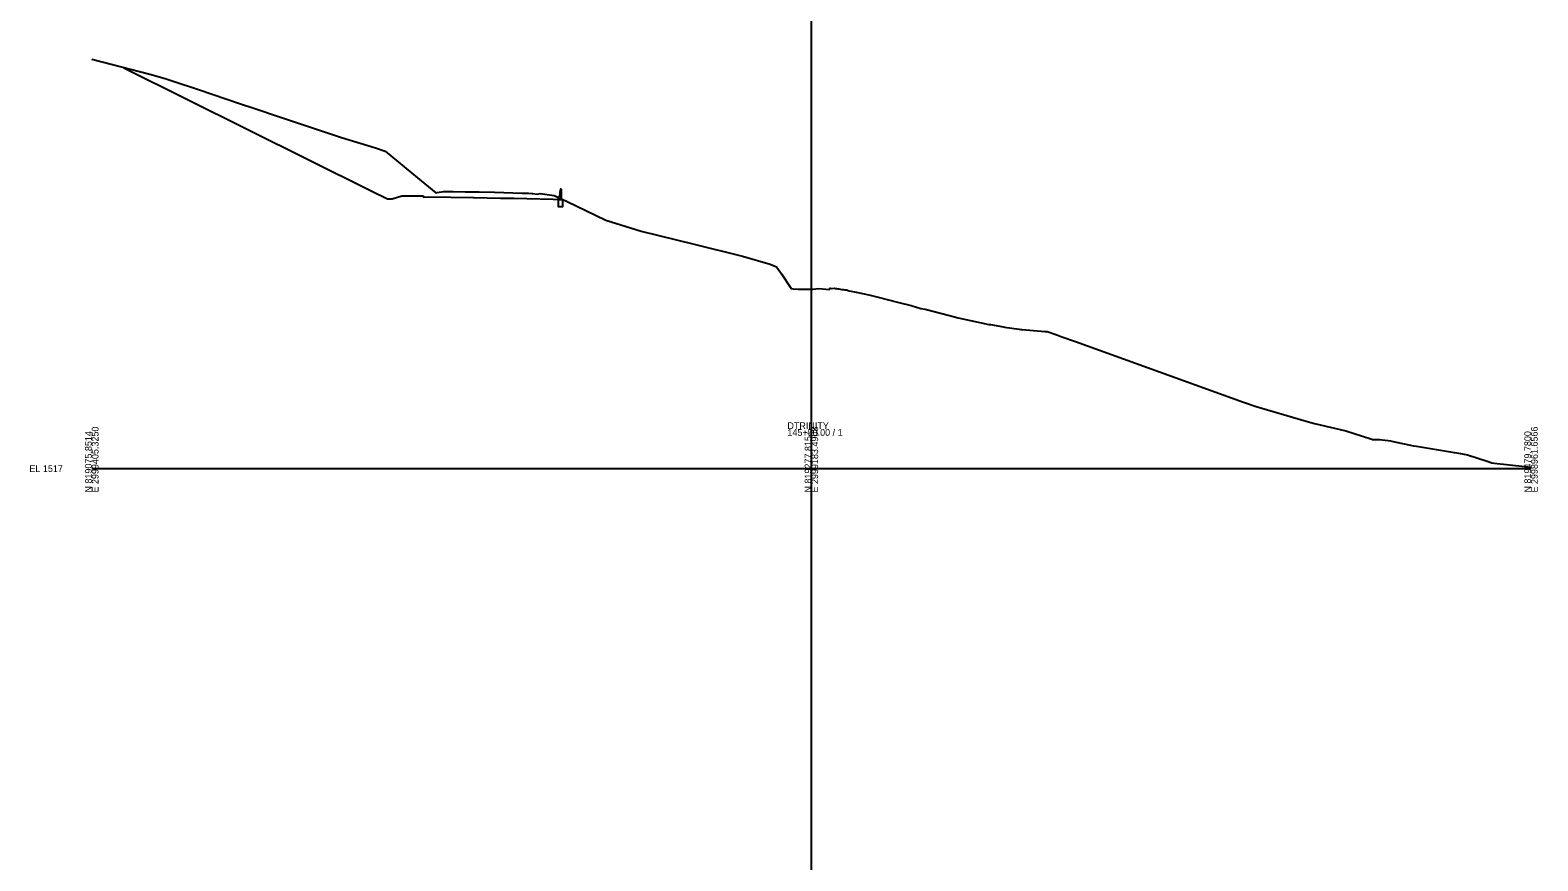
# Model space of a CAD drawing. Extents: x -26 to 603, y -10 to 4805.
# Drawn here: x -26 to 603, y 337 to 683 of the extents above; entities that cross this region are included whole.
import ezdxf

# ---------------------------------------------------------------- set-up
doc = ezdxf.new("R2010")
doc.units = 0
for name, color, linetype in [('DESIGN - SCRATCH - User 1', 7, 'Continuous'), ('DESIGN - SHEET - Light Grid', 7, 'Continuous'), ('DESIGN - TYPICAL - Finished Grade and Subgrade', 7, 'Continuous'), ('SURVEY - GROUND - Top of Ground', 7, 'Continuous')]:
    doc.layers.add(name, color=color, linetype=linetype)

msp = doc.modelspace()

# ---------------------------------------------------------------- linework, layer by layer
at = {"layer": 'DESIGN - SCRATCH - User 1'}
for p, q in [((195.27, 616.35), (194.96, 613.45)), ((195.78, 616.4), (195.33, 616.4)), ((195.78, 612.15), (195.78, 616.4)), ((194.36, 612.38), (194.36, 612.15)), ((194.82, 613.06), (194.37, 612.42))]:
    msp.add_line(p, q, dxfattribs=at)
msp.add_lwpolyline([(194.36, 612.15), (194.36, 609.15), (196.36, 609.15), (196.36, 612.16)], dxfattribs=at)
for centre, radius, start, end in [((194.44, 612.38), 0.0833, 145.00798, 180), ((194.14, 613.54), 0.833, 325.00798, 353.99099)]:
    msp.add_arc(centre, radius, start, end, dxfattribs=at)
at = {"layer": 'DESIGN - SHEET - Light Grid'}
for p, q in [((300, 500), (300, 1012.01)), ((300, 0), (300, 516.44)), ((0, 500), (300, 500)), ((300, 500), (600, 500))]:
    msp.add_line(p, q, dxfattribs=at)
at = {"layer": 'DESIGN - TYPICAL - Finished Grade and Subgrade'}
msp.add_lwpolyline([(13.36, 667.06), (116.43, 615.76), (123.26, 612.37), (124.26, 612.37), (125.26, 612.37), (129.26, 613.71), (130.27, 613.7), (135.27, 613.63), (136.77, 613.61), (137.78, 613.6), (138.27, 613.58), (138.28, 613.1), (140.28, 613.27), (158.95, 612.93), (159.3, 612.92), (170.32, 612.72), (175.88, 612.62), (181.34, 612.52), (192.36, 612.32), (194.36, 612.15), (196.32, 612.16)], dxfattribs=at)
at = {"layer": 'SURVEY - GROUND - Top of Ground'}
msp.add_line((410.1, 552.89), (480.12, 527.62), dxfattribs=at)
for points in [[(0, 670.67), (24.19, 664.39), (30.65, 662.57), (33.99, 661.44), (44.47, 657.98), (61.96, 651.99), (67.53, 650.14), (78.3, 646.59), (104.16, 637.93), (118.28, 633.6), (122.24, 632.33), (135.82, 621.13), (143.41, 614.91), (144.04, 615.07), (146.65, 615.48), (149.09, 615.44), (149.82, 615.45), (150.62, 615.42), (155.67, 615.39), (161.54, 615.3), (167.83, 615.18), (179.42, 614.8), (182.03, 614.73), (183.42, 614.66), (183.86, 614.63), (185.67, 614.4), (186.94, 614.62), (188.9, 614.35), (192.73, 613.74), (197.97, 611.46), (214.36, 603.49), (229.03, 598.89), (251.14, 593.55), (271.24, 588.48), (282.76, 585.24), (285.51, 584.04), (287.57, 581.09), (291.62, 575.06), (292.41, 574.93), (294.45, 574.7), (295.75, 574.71), (300, 574.76), (300.58, 574.77), (303.09, 574.98), (307.55, 574.57), (307.82, 575.18), (308.58, 575.05), (309.66, 575.11), (310.04, 575.08), (310.5, 575.04), (310.98, 574.97), (311.49, 574.88), (312, 574.8), (312.62, 574.68), (313.26, 574.58), (313.88, 574.5), (314.56, 574.42), (315.76, 574.11), (318.69, 573.49), (323.89, 572.37), (325.01, 572.15), (327.34, 571.6), (336.4, 569.26), (341.63, 567.95), (342.04, 567.84), (345.61, 566.73), (347.43, 566.38), (357.61, 563.74), (361.18, 562.8), (366.33, 561.69), (374.01, 560.09), (374.68, 559.97), (378.6, 559.33), (379.21, 559.21), (379.91, 559.08), (380.55, 558.93), (386.57, 558.13), (387.33, 557.99), (387.91, 557.91), (397.38, 557.18), (397.94, 557.14), (398.28, 557.11), (402.29, 555.69), (404.41, 554.96), (410.1, 552.89)], [(480.12, 527.62), (485.42, 525.82), (505.35, 520), (508.26, 519.16), (509.76, 518.81), (522.75, 515.71), (533.16, 512.33), (533.87, 512.1), (534.35, 512.09), (536.94, 512.06), (537.91, 512.01), (539.15, 511.87), (540.45, 511.68), (541.38, 511.54), (542.53, 511.29), (551.04, 509.42), (552.32, 509.27), (566.36, 506.92), (567.89, 506.67), (569.04, 506.51), (573.48, 505.74), (581.67, 503.03), (583.71, 502.35), (584.68, 502.3), (597.44, 500.87), (600, 500.54)]]:
    msp.add_lwpolyline(points, dxfattribs=at)

# ---------------------------------------------------------------- texts
at = {"layer": 'DESIGN - SHEET - Light Grid'}
for s, p in [('N 819075.8514', (0, 490)), ('E 2999405.3250', (2.8, 490)), ('N 819277.8157', (300, 490)), ('E 2999183.4908', (302.8, 490)), ('N 819479.7800', (600, 490)), ('E 2998961.6566', (602.8, 490))]:
    msp.add_text(s, height=2.8, rotation=90, dxfattribs=at).set_placement(p)
for s, p in [('145+50.00 / 1', (290, 513.64)), ('DTRINITY', (290, 516.44)), ('EL 1517', (-26, 498.6))]:
    msp.add_text(s, height=2.8, dxfattribs=at).set_placement(p)

doc.saveas('drawing.dxf')
